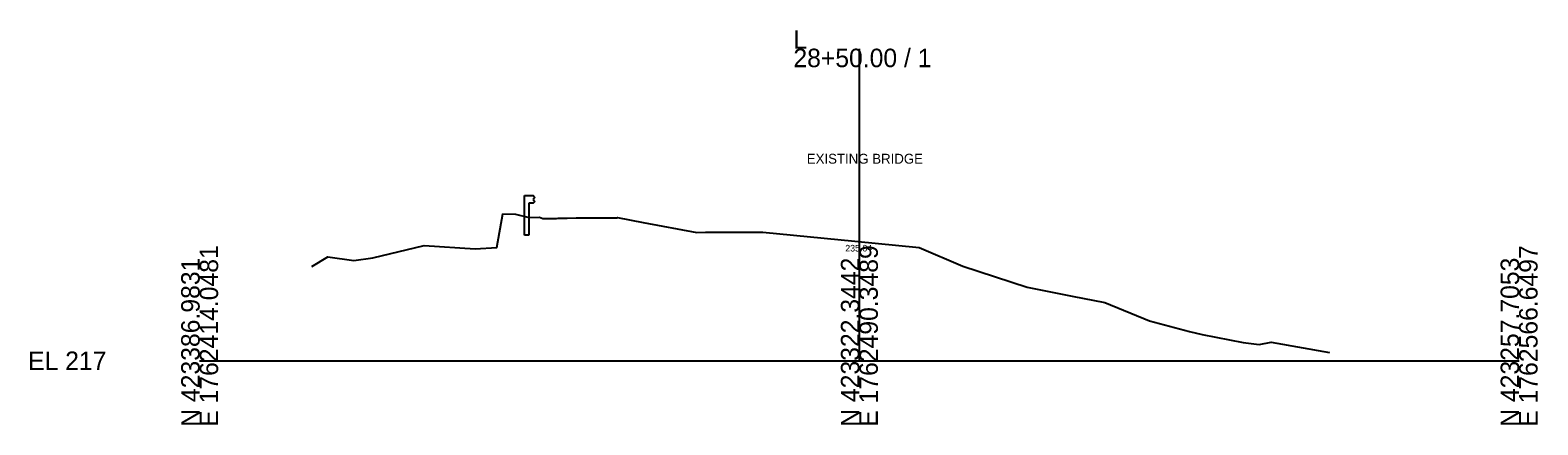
# Model space of a CAD drawing. Extents: x -26 to 3203, y -11010 to 4024.
# Drawn here: x -25.7 to 202.8, y 2990.3 to 3050 of the extents above; entities that cross this region are included whole.
import ezdxf

# ---------------------------------------------------------------- set-up
doc = ezdxf.new("R2010")
doc.units = 0
for name, color, linetype in [('Default', 7, 'Continuous'), ('Exist Cross Section Cell', 7, 'Continuous'), ('Exist XS Center Line Elevation Label', 7, 'Continuous'), ('Exist XS Ground Line', 7, 'Continuous'), ('Prop CMT Guardrail Graphics', 7, 'Continuous'), ('Prop XS SE Text', 7, 'Continuous'), ('Scratch_Level_0', 7, 'Continuous')]:
    doc.layers.add(name, color=color, linetype=linetype)

msp = doc.modelspace()

# ---------------------------------------------------------------- linework, layer by layer
at = {"layer": 'Exist Cross Section Cell'}
for p, q in [((100, 3000), (100, 3047.24)), ((0, 3000), (100, 3000)), ((100, 3000), (200, 3000))]:
    msp.add_line(p, q, dxfattribs=at)
at = {"layer": 'Exist XS Ground Line'}
msp.add_lwpolyline([(16.98, 3014.28), (19.42, 3015.75), (23.37, 3015.16), (26.27, 3015.58), (34.01, 3017.43), (41.74, 3016.96), (45.07, 3017.14), (45.93, 3022.22), (47.85, 3022.2), (49.93, 3021.71), (51.53, 3021.75), (52, 3021.54), (52.47, 3021.55), (52.65, 3021.55), (54.07, 3021.55), (54.36, 3021.56), (55.73, 3021.58), (57.07, 3021.61), (57.25, 3021.61), (58.13, 3021.63), (58.35, 3021.62), (59.43, 3021.62), (60.3, 3021.64), (62.74, 3021.65), (62.92, 3021.65), (63.05, 3021.65), (63.25, 3021.65), (63.32, 3021.71), (67.23, 3020.95), (75.38, 3019.39), (76.69, 3019.46), (85.35, 3019.49), (99.3, 3018.11), (109.04, 3017.13), (115.68, 3014.32), (125.44, 3011.14), (132.27, 3009.77), (137.19, 3008.8), (143.99, 3006.03), (150.04, 3004.44), (151.97, 3003.97), (158.18, 3002.76), (160.6, 3002.47), (162.44, 3002.8), (171.27, 3001.26)], dxfattribs=at)
msp.add_lwpolyline([(16.98, 3014.28), (19.42, 3015.75), (23.37, 3015.16), (26.27, 3015.58), (34.01, 3017.43), (41.74, 3016.96), (45.07, 3017.14), (45.93, 3022.22), (47.85, 3022.2), (49.93, 3021.71), (51.53, 3021.75), (52, 3021.54), (52.47, 3021.55), (52.65, 3021.55), (54.07, 3021.55), (54.36, 3021.56), (55.73, 3021.58), (57.07, 3021.61), (57.25, 3021.61), (58.13, 3021.63), (58.35, 3021.62), (59.43, 3021.62), (60.3, 3021.64), (62.74, 3021.65), (62.92, 3021.65), (63.05, 3021.65), (63.25, 3021.65), (63.32, 3021.71), (67.23, 3020.95), (75.38, 3019.39), (76.69, 3019.46), (85.35, 3019.49), (99.3, 3018.11), (109.04, 3017.13), (115.68, 3014.32), (125.44, 3011.14), (132.27, 3009.77), (137.19, 3008.8), (143.99, 3006.03), (150.04, 3004.44), (151.97, 3003.97), (158.18, 3002.76), (160.6, 3002.47), (162.44, 3002.8), (171.27, 3001.26)], dxfattribs=at)
msp.add_lwpolyline([(16.98, 3014.28), (19.42, 3015.75), (23.37, 3015.16), (26.27, 3015.58), (34.01, 3017.43), (41.74, 3016.96), (45.07, 3017.14), (45.93, 3022.22), (47.85, 3022.2), (49.93, 3021.71), (51.53, 3021.75), (52, 3021.54), (52.47, 3021.55), (52.65, 3021.55), (54.07, 3021.55), (54.36, 3021.56), (55.73, 3021.58), (57.07, 3021.61), (57.25, 3021.61), (58.13, 3021.63), (58.35, 3021.62), (59.43, 3021.62), (60.3, 3021.64), (62.74, 3021.65), (62.92, 3021.65), (63.05, 3021.65), (63.25, 3021.65), (63.32, 3021.71), (67.23, 3020.95), (75.38, 3019.39), (76.69, 3019.46), (85.35, 3019.49), (99.3, 3018.11), (109.04, 3017.13), (115.68, 3014.32), (125.44, 3011.14), (132.27, 3009.77), (137.19, 3008.8), (143.99, 3006.03), (150.04, 3004.44), (151.97, 3003.97), (158.18, 3002.76), (160.6, 3002.47), (162.44, 3002.8), (171.27, 3001.26)], dxfattribs=at)
msp.add_lwpolyline([(16.98, 3014.28), (19.42, 3015.75), (23.37, 3015.16), (26.27, 3015.58), (34.01, 3017.43), (41.74, 3016.96), (45.07, 3017.14), (45.93, 3022.22), (47.85, 3022.2), (49.93, 3021.71), (51.53, 3021.75), (52, 3021.54), (52.47, 3021.55), (52.65, 3021.55), (54.07, 3021.55), (54.36, 3021.56), (55.73, 3021.58), (57.07, 3021.61), (57.25, 3021.61), (58.13, 3021.63), (58.35, 3021.62), (59.43, 3021.62), (60.3, 3021.64), (62.74, 3021.65), (62.92, 3021.65), (63.05, 3021.65), (63.25, 3021.65), (63.32, 3021.71), (67.23, 3020.95), (75.38, 3019.39), (76.69, 3019.46), (85.35, 3019.49), (99.3, 3018.11), (109.04, 3017.13), (115.68, 3014.32), (125.44, 3011.14), (132.27, 3009.77), (137.19, 3008.8), (143.99, 3006.03), (150.04, 3004.44), (151.97, 3003.97), (158.18, 3002.76), (160.6, 3002.47), (162.44, 3002.8), (171.27, 3001.26)], dxfattribs=at)
msp.add_lwpolyline([(16.98, 3014.28), (19.42, 3015.75), (23.37, 3015.16), (26.27, 3015.58), (34.01, 3017.43), (41.74, 3016.96), (45.07, 3017.14), (45.93, 3022.22), (47.85, 3022.2), (49.93, 3021.71), (51.53, 3021.75), (52, 3021.54), (52.47, 3021.55), (52.65, 3021.55), (54.07, 3021.55), (54.36, 3021.56), (55.73, 3021.58), (57.07, 3021.61), (57.25, 3021.61), (58.13, 3021.63), (58.35, 3021.62), (59.43, 3021.62), (60.3, 3021.64), (62.74, 3021.65), (62.92, 3021.65), (63.05, 3021.65), (63.25, 3021.65), (63.32, 3021.71), (67.23, 3020.95), (75.38, 3019.39), (76.69, 3019.46), (85.35, 3019.49), (99.3, 3018.11), (109.04, 3017.13), (115.68, 3014.32), (125.44, 3011.14), (132.27, 3009.77), (137.19, 3008.8), (143.99, 3006.03), (150.04, 3004.44), (151.97, 3003.97), (158.18, 3002.76), (160.6, 3002.47), (162.44, 3002.8), (171.27, 3001.26)], dxfattribs=at)
at = {"layer": 'Prop CMT Guardrail Graphics'}
for points in [[(49.22, 3019), (49.22, 3025)], [(49.22, 3025), (50.55, 3025), (50.82, 3024.71)], [(50.82, 3024.13), (50.55, 3023.84), (49.89, 3023.84)], [(49.89, 3023.84), (49.89, 3019)], [(50.82, 3024.71), (50.55, 3024.42)], [(50.55, 3024.42), (50.82, 3024.13)], [(49.89, 3019), (49.22, 3019)]]:
    msp.add_lwpolyline(points, dxfattribs=at)

# ---------------------------------------------------------------- texts
at = {"layer": 'Default'}
msp.add_text('-', height=0.0001, dxfattribs=at).set_placement((0, 3000))
at = {"layer": 'Exist Cross Section Cell'}
for s, p in [('L', (90, 3047.24)), ('28+50.00 / 1', (90, 3044.44)), ('EL 217', (-26, 2998.6))]:
    msp.add_text(s, height=2.8, dxfattribs=at).set_placement(p)
for s, p in [('E 1762414.0481', (2.8, 2990)), ('E 1762490.3489', (102.8, 2990)), ('E 1762566.6497', (202.8, 2990)), ('N 423386.9831', (0, 2990)), ('N 423322.3442', (100, 2990)), ('N 423257.7053', (200, 2990))]:
    msp.add_text(s, height=2.8, rotation=90, dxfattribs=at).set_placement(p)
at = {"layer": 'Exist XS Center Line Elevation Label'}
msp.add_text('235.04', height=1, dxfattribs=at).set_placement((97.86, 3016.54))
at = {"layer": 'Prop XS SE Text'}
msp.add_text('EXISTING BRIDGE', height=1.5, rotation=360, dxfattribs=at).set_placement((92.03, 3029.83))
at = {"layer": 'Scratch_Level_0'}
for s, p in [('RT_GR_Graphics Out 03', (49.03, 3024.99)), ('RT_GR_Graphics Out 06', (49.69, 3023.83)), ('RT_GR_Graphics Out 02', (50.36, 3024.99)), ('RT_GR_Graphics Out 09', (50.36, 3024.41)), ('RT_GR_Graphics Out 07', (50.36, 3023.83)), ('RT_GR_Graphics Out 08', (50.63, 3024.12)), ('RT_GR_Out', (50.74, 3024.7)), ('RT_GR_Graphics Out 04', (49.03, 3018.99)), ('RT_GR_Graphics Out 05', (49.69, 3018.99))]:
    msp.add_text(s, height=0.02, dxfattribs=at).set_placement(p)

doc.saveas('drawing.dxf')
